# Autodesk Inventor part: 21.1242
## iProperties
Created: 2006-02
Part Number: 21.1242
Material: Steel, Mild
Description: M6X25 SHCS
Document SubType Name: Modeling
Standard: DIN 7984
Designer: Andy Moles
Standards Organization: DIN
Language: en-US
Size Designation: M6 x 25
Categories: <MemberInstance><Categories><Category DisplayName="Fasteners" InternalName="e4da775c-781d-43d5-af7c-5136215cf5a6" Mnemonic="FSTN"><Category DisplayName="Bolts"
Density: 7.86 g/cm^3
Mass: 7.59699 g
Surface Area: 7.83808 cm^2
Volume: 0.966539 cm^3
Vendor: S
Author: Andy Moles
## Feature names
1. Body [Revolution]
2. Slot [Extrusion]
3. Fillet1
4. Chamfer1
